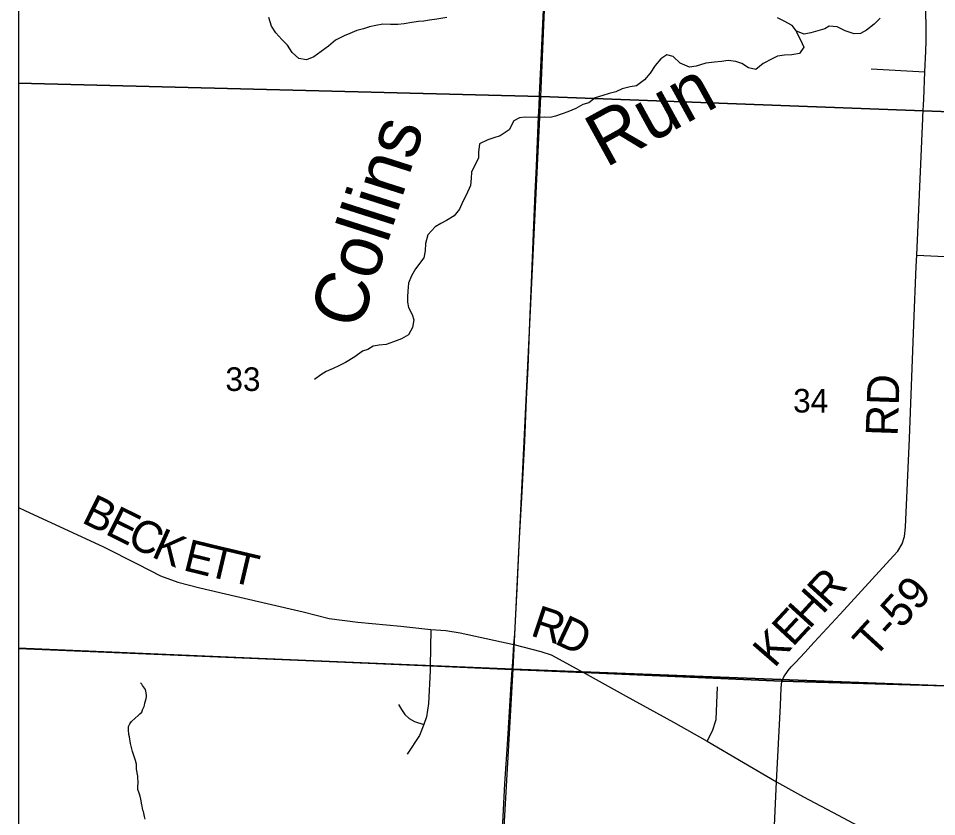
# Model space of a CAD drawing. Extents: x 0 to 34, y 0 to 22.
# Drawn here: x 2.1 to 3.73, y 17.505 to 18.922 of the extents above; entities that cross this region are included whole.
import ezdxf

# ---------------------------------------------------------------- set-up
doc = ezdxf.new("R2010")
doc.units = 0
for name, color, linetype in [('Default', 7, 'Continuous'), ('GM_X_City_Street', 7, 'Continuous'), ('GM_X_County_Road', 7, 'Continuous'), ('GM_X_County_Road_Text', 7, 'Continuous'), ('GM_X_Minor_River', 7, 'Continuous'), ('GM_X_Minor_River_Text', 7, 'Continuous'), ('GM_X_Section', 7, 'Continuous'), ('GM_X_Section_Text', 7, 'Continuous'), ('GM_X_State_Route', 7, 'Continuous'), ('GM_X_Township_Road', 7, 'Continuous'), ('GM_X_Township_Road_Text', 7, 'Continuous'), ('SH_Data', 7, 'Continuous')]:
    doc.layers.add(name, color=color, linetype=linetype)

msp = doc.modelspace()

# ---------------------------------------------------------------- linework, layer by layer
at = {"layer": 'Default'}
for points in [[(6.0871, 20.9), (2.1, 20.9), (2.1, 17.8044), (2.8305, 17.7727), (2.976, 17.7664), (3.1037, 17.7609), (3.4544, 17.7458), (3.7662, 17.7368), (3.9904, 17.7296), (4.1165, 17.7286), (4.1238, 17.7269), (4.1354, 17.7264), (4.1969, 17.7246), (4.2769, 17.7222), (4.4203, 17.718), (4.506, 17.7155), (4.6237, 17.7121), (4.6735, 17.7102), (4.763, 17.7084), (4.9045, 17.7039), (4.98, 17.7015), (5.0396, 17.6997)], [(5.0396, 17.6997), (4.98, 17.7015), (4.9045, 17.7039), (4.763, 17.7084), (4.6735, 17.7102), (4.6237, 17.7121), (4.506, 17.7155), (4.4203, 17.718), (4.2769, 17.7222), (4.1969, 17.7246), (4.1354, 17.7264), (4.1238, 17.7269), (4.1165, 17.7286), (3.9904, 17.7296), (3.7662, 17.7368), (3.4544, 17.7458), (3.1037, 17.7609), (2.976, 17.7664), (2.8305, 17.7727), (2.1, 17.8044), (2.1, 14.1), (5.898, 14.1)]]:
    msp.add_lwpolyline(points, dxfattribs=at)
for points in [[(2.1, 19.8201), (2.1, 18.8072), (3.0273, 18.7832), (3.0692, 19.7796)], [(2.1, 18.8072), (2.1, 17.8037), (2.9781, 17.7672), (3.0273, 18.7832)], [(2.1, 17.8037), (2.1, 16.814), (2.9224, 16.7901), (2.9781, 17.7672)]]:
    msp.add_lwpolyline(points, close=True, dxfattribs=at)
at = {"layer": 'GM_X_City_Street'}
msp.add_line((3.6132, 18.8327), (3.7084, 18.827), dxfattribs=at)
at = {"layer": 'GM_X_County_Road'}
for points in [[(2.1, 18.0541), (2.1128, 18.0482), (2.2496, 17.9849), (2.3121, 17.9534), (2.352, 17.9329), (2.383, 17.9214), (2.4219, 17.9116), (2.4851, 17.8968), (2.6054, 17.8685), (2.6517, 17.8572), (2.7024, 17.8504), (2.7788, 17.8431), (2.8317, 17.8375), (2.8588, 17.8356), (2.8838, 17.8314), (2.9435, 17.8183), (2.9793, 17.8109)], [(2.9793, 17.8109), (3.027, 17.7983), (3.0454, 17.7923), (3.0664, 17.7815), (3.0896, 17.7683), (3.1006, 17.7622)], [(3.1006, 17.7622), (3.104, 17.7604), (3.1788, 17.7191), (3.2626, 17.6727), (3.3221, 17.6393), (3.3866, 17.6014), (3.4456, 17.5672)], [(3.4456, 17.5672), (3.4931, 17.5407), (3.5546, 17.5077), (3.6491, 17.4574), (3.7489, 17.4049), (3.8278, 17.3631), (4.0032, 17.2687), (4.1749, 17.1732), (4.3746, 17.0628), (4.4408, 17.0257), (4.6086, 16.9333), (4.7096, 16.8784), (4.747, 16.8517), (4.7876, 16.8185), (4.9398, 16.7), (5, 16.6522), (5.063, 16.6012), (5.161, 16.519), (5.2098, 16.4792), (5.2812, 16.4203), (5.3347, 16.377), (5.3972, 16.3264)]]:
    msp.add_lwpolyline(points, dxfattribs=at)
at = {"layer": 'GM_X_Minor_River'}
for points in [[(2.8601, 18.9235), (2.8425, 18.9206), (2.8296, 18.9186), (2.8197, 18.9173), (2.8101, 18.9164), (2.7983, 18.9144), (2.7846, 18.9125), (2.7732, 18.9113), (2.7603, 18.9112), (2.7466, 18.9115), (2.7344, 18.9092), (2.7233, 18.9068), (2.7126, 18.9036), (2.7007, 18.9005), (2.6881, 18.8951), (2.6781, 18.8908), (2.6627, 18.8836), (2.6503, 18.8729), (2.6371, 18.8633), (2.6244, 18.8538), (2.6113, 18.8484), (2.5977, 18.8506), (2.5858, 18.8615), (2.5774, 18.8747), (2.5674, 18.8844), (2.5567, 18.8965), (2.549, 18.9084), (2.5445, 18.9233)], [(3.5313, 18.9032), (3.5061, 18.8962), (3.4943, 18.8939), (3.4811, 18.8995), (3.4734, 18.9096), (3.4588, 18.9171), (3.4472, 18.9231)], [(3.6296, 18.9223), (3.6184, 18.9119), (3.6049, 18.9011), (3.5942, 18.8952), (3.5831, 18.8947), (3.5673, 18.8999), (3.553, 18.907), (3.5386, 18.9084), (3.5313, 18.9032)], [(3.4811, 18.8995), (3.4807, 18.8976), (3.4879, 18.8837), (3.4941, 18.8707), (3.4862, 18.8599), (3.4728, 18.8575), (3.4595, 18.8567), (3.4473, 18.8547), (3.4377, 18.85), (3.4215, 18.8417), (3.4087, 18.831), (3.3959, 18.8343), (3.3836, 18.8419), (3.373, 18.8455), (3.3594, 18.847), (3.3476, 18.8454), (3.3354, 18.8442), (3.3202, 18.8423), (3.3029, 18.837), (3.2911, 18.8354), (3.2746, 18.8427), (3.262, 18.8544), (3.2507, 18.8573), (3.2402, 18.85), (3.23, 18.8381), (3.2214, 18.825), (3.2112, 18.8131), (3.1972, 18.802), (3.1858, 18.8004), (3.1716, 18.7969), (3.1601, 18.7919), (3.1486, 18.7888), (3.1372, 18.7849), (3.1234, 18.7807), (3.1125, 18.7722), (3.1014, 18.769), (3.0891, 18.7621), (3.0753, 18.756), (3.0649, 18.7525), (3.0531, 18.7486), (3.0435, 18.7462), (3.0329, 18.7464), (3.0196, 18.746), (2.9991, 18.7465), (2.9892, 18.7452), (2.9792, 18.7401), (2.9708, 18.7244), (2.9549, 18.7138), (2.9438, 18.7102), (2.9331, 18.7067), (2.9185, 18.6995), (2.9166, 18.6843), (2.9163, 18.6741), (2.9095, 18.6602), (2.9043, 18.6493), (2.9037, 18.6387), (2.9026, 18.6254), (2.8949, 18.6085), (2.8889, 18.5968), (2.8829, 18.5833), (2.8731, 18.5718), (2.8596, 18.5634), (2.8499, 18.5579), (2.8399, 18.5521), (2.8266, 18.5376), (2.8224, 18.5225), (2.8217, 18.5092), (2.8195, 18.4971), (2.805, 18.4777), (2.7978, 18.465), (2.7922, 18.4522), (2.791, 18.4378), (2.7904, 18.4279), (2.7905, 18.4184), (2.7922, 18.4089), (2.7987, 18.3966), (2.8019, 18.387), (2.7996, 18.3734), (2.7925, 18.3602), (2.7801, 18.353), (2.7656, 18.348), (2.7525, 18.343), (2.7403, 18.3418), (2.7297, 18.3401), (2.72, 18.3343), (2.7104, 18.3311), (2.6969, 18.3216), (2.6803, 18.3113), (2.6684, 18.3056), (2.6588, 18.3005), (2.6461, 18.2951), (2.6365, 18.2896), (2.6256, 18.2812)], [(2.3252, 17.5009), (2.3238, 17.5055), (2.3221, 17.5143), (2.321, 17.517), (2.3196, 17.5239), (2.3193, 17.5265), (2.3176, 17.5365), (2.3159, 17.5414), (2.3141, 17.5472), (2.3119, 17.5533), (2.3121, 17.5598), (2.3126, 17.5643), (2.3121, 17.5772), (2.3097, 17.5898), (2.3096, 17.5986), (2.3078, 17.6047), (2.3025, 17.6208), (2.3007, 17.628), (2.299, 17.6353), (2.297, 17.6471), (2.296, 17.6513), (2.2954, 17.6593), (2.2955, 17.6654), (2.2979, 17.6703), (2.3007, 17.6744), (2.3073, 17.6799), (2.3127, 17.6847), (2.3158, 17.6877), (2.3189, 17.691), (2.3202, 17.6948), (2.3234, 17.7008), (2.3238, 17.703), (2.3246, 17.7064), (2.3267, 17.7147), (2.3272, 17.7178), (2.3273, 17.7216), (2.3263, 17.7281), (2.3256, 17.7311), (2.32, 17.7381), (2.3189, 17.7404), (2.3167, 17.7427)]]:
    msp.add_lwpolyline(points, dxfattribs=at)
at = {"layer": 'GM_X_Section'}
for points in [[(3.0692, 19.7796), (4.0623, 19.7415), (4.0218, 18.7461), (3.0273, 18.7832)], [(3.0273, 18.7832), (4.0218, 18.7461), (3.996, 17.7284), (3.9286, 17.7304), (2.9781, 17.7672)], [(2.9781, 17.7672), (3.9286, 17.7304), (3.904, 16.7335), (3.4696, 16.7535), (3.47, 16.7707), (2.9224, 16.7901)]]:
    msp.add_lwpolyline(points, close=True, dxfattribs=at)
at = {"layer": 'GM_X_State_Route'}
for points in [[(3.0248, 18.7867), (3.0253, 18.7987), (3.0277, 18.848), (3.0314, 18.9253), (3.0324, 18.9483), (3.0344, 18.9941), (3.0363, 19.0344), (3.0384, 19.0751), (3.0419, 19.1453), (3.0445, 19.1957), (3.0461, 19.2315), (3.0474, 19.269)], [(2.9793, 17.8109), (2.9809, 17.8297), (2.9849, 17.9095), (2.9895, 17.9996), (2.9939, 18.0816), (2.9986, 18.1716), (3.002, 18.246), (3.0044, 18.3023), (3.0079, 18.3829), (3.0106, 18.4525), (3.0147, 18.5555), (3.0169, 18.6122), (3.0193, 18.6595), (3.0229, 18.7477), (3.0241, 18.7667), (3.0248, 18.7867)], [(2.9589, 17.4823), (2.9635, 17.5634), (2.9685, 17.6425), (2.9719, 17.7013), (2.9737, 17.7307), (2.9763, 17.7659), (2.9773, 17.7797), (2.9793, 17.8109)]]:
    msp.add_lwpolyline(points, dxfattribs=at)
at = {"layer": 'GM_X_Township_Road'}
for p, q in [((3.6967, 18.5558), (3.7051, 18.7441)), ((3.6943, 18.502), (3.7438, 18.4991))]:
    msp.add_line(p, q, dxfattribs=at)
for points in [[(3.7051, 18.7441), (3.7053, 18.7481), (3.7069, 18.7785), (3.7084, 18.827), (3.7105, 18.8636), (3.7111, 18.8823), (3.7109, 18.9116), (3.71, 18.9461), (3.7034, 18.9808), (3.6868, 19.0418), (3.6771, 19.0626), (3.6594, 19.0934), (3.6557, 19.1098), (3.6491, 19.1475), (3.6494, 19.1722), (3.6533, 19.1904), (3.6565, 19.2129), (3.6608, 19.2383), (3.6633, 19.2574)], [(3.4716, 17.7709), (3.479, 17.7791), (3.4958, 17.7967), (3.5123, 17.8152), (3.5584, 17.8647), (3.6529, 17.9681), (3.6604, 17.9765), (3.6683, 17.9895), (3.6723, 18.0025), (3.6741, 18.0189), (3.6815, 18.1766), (3.6889, 18.3785), (3.6932, 18.4818), (3.6943, 18.502), (3.6967, 18.5558)], [(2.8317, 17.8375), (2.8307, 17.7722), (2.8307, 17.7676)], [(2.8307, 17.7676), (2.8306, 17.7639), (2.828, 17.7061), (2.8245, 17.6823), (2.8197, 17.6691), (2.8116, 17.6492), (2.7902, 17.616)], [(3.4456, 17.5672), (3.4523, 17.7025), (3.4534, 17.7336), (3.4547, 17.7453), (3.4581, 17.7537), (3.4662, 17.7649), (3.4716, 17.7709)], [(3.3221, 17.6393), (3.3318, 17.6578), (3.3381, 17.6778), (3.3407, 17.7354)], [(2.7743, 17.7045), (2.7798, 17.6954), (2.7858, 17.6865), (2.7936, 17.6793), (2.8027, 17.6744), (2.8197, 17.6691)], [(3.4128, 16.7769), (3.4121, 16.7944), (3.4147, 16.8656), (3.4236, 17.1118), (3.4295, 17.206), (3.4361, 17.3704), (3.4416, 17.4895), (3.4456, 17.5672)]]:
    msp.add_lwpolyline(points, dxfattribs=at)
at = {"layer": 'SH_Data'}
msp.add_line((2.1, 20.9), (2.1, 14.1), dxfattribs=at)

# ---------------------------------------------------------------- texts
at = {"layer": 'GM_X_County_Road_Text'}
for s, rotation, p in [('B', 333.6922, (2.2101, 18.0283)), ('E', 333.6884, (2.252, 18.0076)), ('C', 333.7323, (2.2901, 17.9888)), ('K', 335.9115, (2.3341, 17.9671)), ('E', 346.3138, (2.3904, 17.9431)), ('T', 346.7378, (2.4321, 17.9329)), ('T', 346.7558, (2.4735, 17.9231)), ('R', 341.5948, (3.0068, 17.8274)), ('D', 334.7795, (3.0494, 17.8133))]:
    msp.add_text(s, height=0.0568, rotation=rotation, dxfattribs=at).set_placement(p)
at = {"layer": 'GM_X_Minor_River_Text'}
for s, height, rotation, p in [('Run', 0.09469, 28.8105, (3.1421, 18.6561)), ('Collins', 0.09467, 72.3175, (2.7056, 18.3665))]:
    msp.add_text(s, height=height, rotation=rotation, dxfattribs=at).set_placement(p)
at = {"layer": 'GM_X_Section_Text'}
for s, p in [('33', (2.4674, 18.2608)), ('34', (3.4749, 18.2225))]:
    msp.add_text(s, height=0.04186, rotation=0, dxfattribs=at).set_placement(p)
at = {"layer": 'GM_X_Township_Road_Text'}
for s, height, rotation, p in [('RD', 0.05682, 88.025, (3.6603, 18.1798)), ('R', 0.0568, 47.5958, (3.5371, 17.8736)), ('T-59', 0.05682, 47.4866, (3.6182, 17.7842)), ('H', 0.0568, 47.5816, (3.5034, 17.8366)), ('E', 0.0568, 47.0274, (3.474, 17.8051)), ('K', 0.0568, 49.03, (3.4416, 17.7677))]:
    msp.add_text(s, height=height, rotation=rotation, dxfattribs=at).set_placement(p)

doc.saveas('drawing.dxf')
